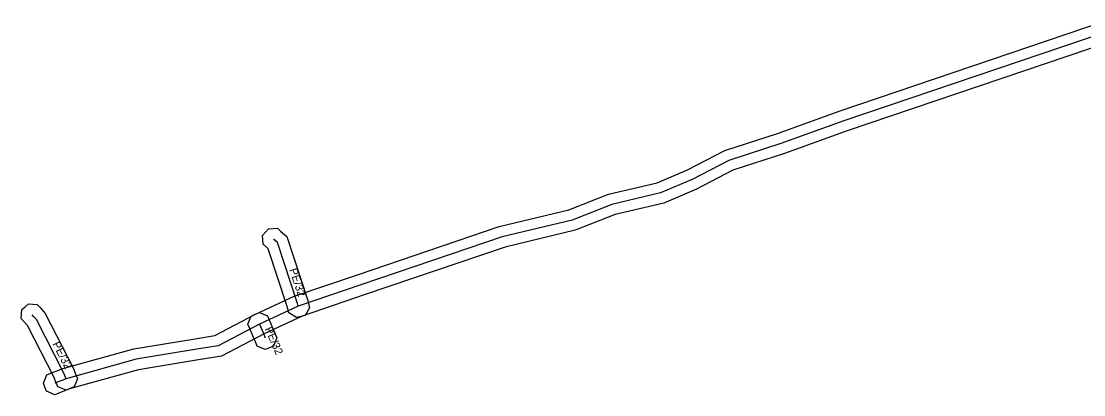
# Model space of a CAD drawing. Extents: x -677728 to -676939, y -1057290 to -1056960.
# Drawn here: x -677728 to -677628.5, y -1057289.7 to -1057254.8 of the extents above; entities that cross this region are included whole.
import ezdxf

# ---------------------------------------------------------------- set-up
doc = ezdxf.new("R2010")
doc.units = 0
for name, color, linetype in [('1', 7, 'Continuous'), ('24', 7, 'Continuous'), ('30', 7, 'Continuous')]:
    doc.layers.add(name, color=color, linetype=linetype)

msp = doc.modelspace()

# ---------------------------------------------------------------- linework, layer by layer
at = {"layer": '1'}
msp.add_lwpolyline([(-677625.904, -1057256.662), (-677650.62, -1057265.024), (-677656.505, -1057267.146), (-677661.321, -1057268.715), (-677664.734, -1057270.496), (-677667.789, -1057271.784), (-677672.371, -1057272.867), (-677676.1, -1057274.326), (-677682.662, -1057275.902), (-677695.769, -1057280.357), (-677701.687, -1057282.36), (-677705.235, -1057284.016), (-677709.232, -1057286.123), (-677711.402, -1057286.457), (-677717.024, -1057287.388), (-677723.48, -1057289.179), (-677724.479, -1057289.578), (-677724.863, -1057289.732), (-677725.624, -1057289.406), (-677725.778, -1057289.021), (-677725.932, -1057288.637), (-677725.606, -1057287.876), (-677725.221, -1057287.722), (-677724.12, -1057287.281), (-677717.456, -1057285.432), (-677711.718, -1057284.483), (-677709.868, -1057284.197), (-677706.125, -1057282.224), (-677702.433, -1057280.5), (-677696.411, -1057278.463), (-677683.218, -1057273.978), (-677676.7, -1057272.414), (-677672.969, -1057270.953), (-677668.411, -1057269.876), (-677665.586, -1057268.684), (-677662.099, -1057266.865), (-677657.155, -1057265.254), (-677651.28, -1057263.136), (-677626.516, -1057254.758)], dxfattribs=at)
for points in [[(-677702.93, -1057282.075), (-677703.03, -1057281.673), (-677703.081, -1057281.467), (-677704.856, -1057276.059), (-677705.024, -1057275.91), (-677705.335, -1057275.636), (-677705.386, -1057274.809), (-677705.111, -1057274.499), (-677704.837, -1057274.188), (-677704.01, -1057274.137), (-677703.7, -1057274.412), (-677703.124, -1057274.921), (-677701.159, -1057280.913), (-677701.09, -1057281.187), (-677700.989, -1057281.589), (-677701.415, -1057282.3), (-677701.817, -1057282.4), (-677702.219, -1057282.501)], [(-677724.57, -1057288.991), (-677724.726, -1057288.607), (-677724.95, -1057288.057), (-677727.413, -1057283.257), (-677727.729, -1057282.897), (-677728.002, -1057282.586), (-677727.949, -1057281.759), (-677727.638, -1057281.486), (-677727.327, -1057281.213), (-677726.5, -1057281.266), (-677726.227, -1057281.577), (-677725.747, -1057282.123), (-677723.13, -1057287.223), (-677722.874, -1057287.853), (-677722.718, -1057288.237), (-677723.039, -1057289), (-677723.423, -1057289.156), (-677723.807, -1057289.312)], [(-677704.926, -1057282.344), (-677704.762, -1057282.725), (-677704.448, -1057283.452), (-677704.212, -1057284.025), (-677704.055, -1057284.408), (-677704.373, -1057285.173), (-677704.756, -1057285.331), (-677705.139, -1057285.488), (-677705.904, -1057285.17), (-677706.062, -1057284.787), (-677706.292, -1057284.228), (-677706.598, -1057283.515), (-677706.762, -1057283.135), (-677706.456, -1057282.366), (-677706.075, -1057282.202), (-677705.695, -1057282.038)]]:
    msp.add_lwpolyline(points, close=True, dxfattribs=at)
at = {"layer": '24'}
for points in [[(-677626.21, -1057255.71), (-677650.95, -1057264.08), (-677656.83, -1057266.2), (-677661.71, -1057267.79), (-677665.16, -1057269.59), (-677668.1, -1057270.83), (-677672.67, -1057271.91), (-677676.4, -1057273.37), (-677682.94, -1057274.94), (-677696.09, -1057279.41), (-677702.06, -1057281.43), (-677705.68, -1057283.12), (-677709.55, -1057285.16), (-677711.56, -1057285.47), (-677717.24, -1057286.41), (-677723.8, -1057288.23), (-677724.85, -1057288.65)], [(-677702.06, -1057281.43), (-677702.12, -1057281.19), (-677703.99, -1057275.49), (-677704.33, -1057275.19), (-677704.362, -1057275.161)], [(-677723.8, -1057288.23), (-677724.04, -1057287.64), (-677726.58, -1057282.69), (-677726.87, -1057282.36), (-677726.978, -1057282.237)], [(-677705.68, -1057283.12), (-677705.37, -1057283.84), (-677705.137, -1057284.406)]]:
    msp.add_lwpolyline(points, dxfattribs=at)

# ---------------------------------------------------------------- texts
at = {"layer": '30'}
for rotation, p in [(288.16312, (-677702.894, -1057278.022)), (293.29456, (-677705.204, -1057283.561)), (297.16378, (-677725.102, -1057284.98))]:
    msp.add_text('PE/32', height=0.75, rotation=rotation, dxfattribs=at).set_placement(p)

doc.saveas('drawing.dxf')
